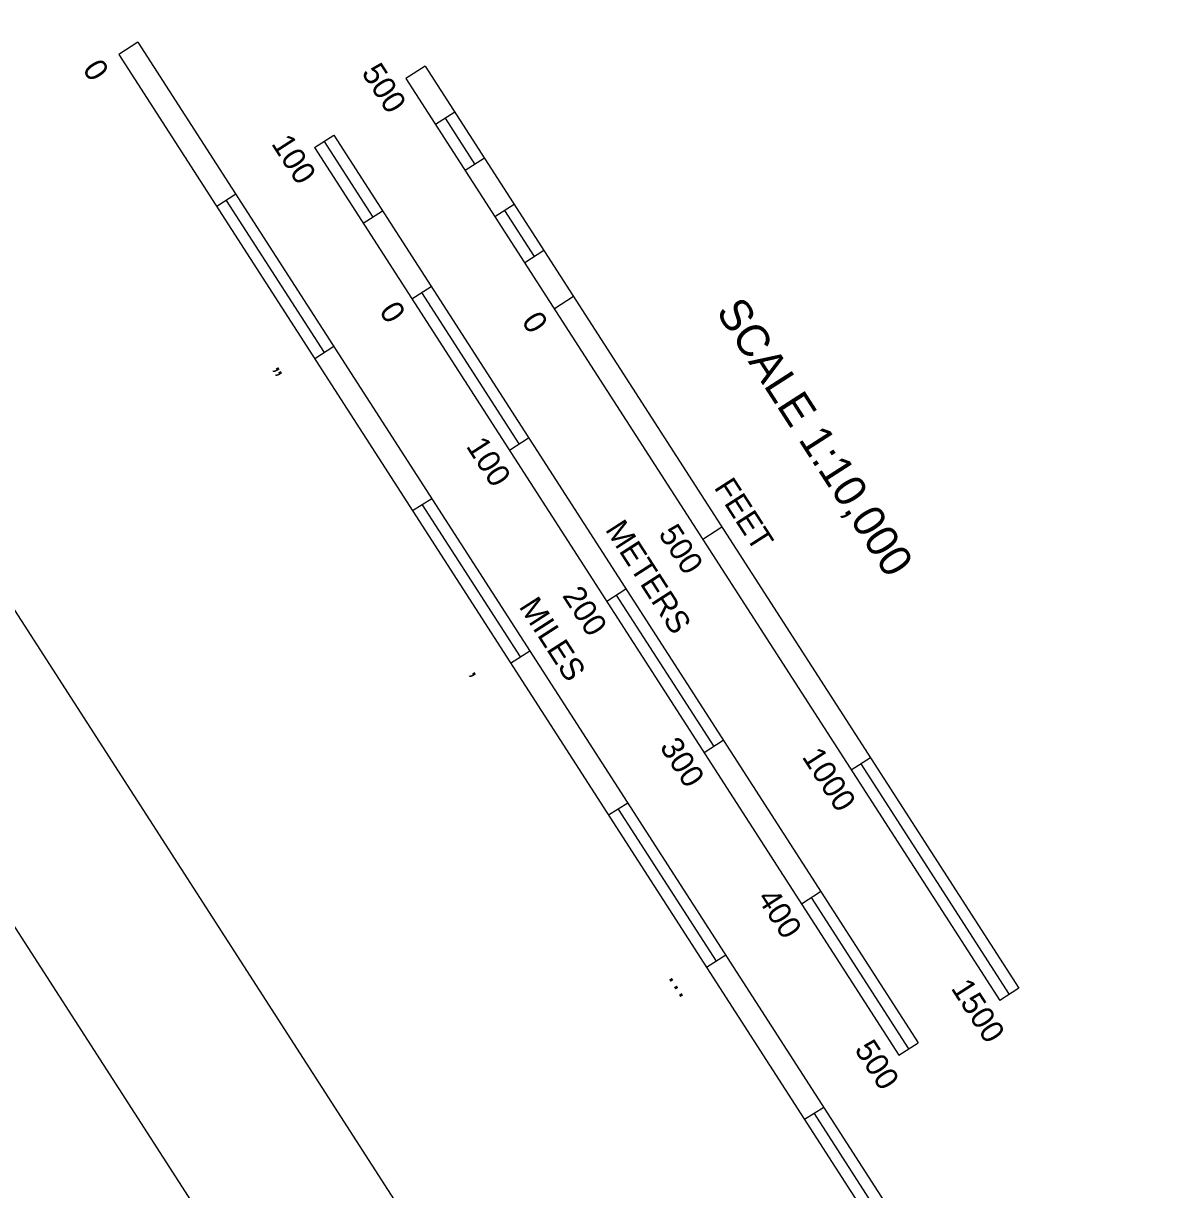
# Model space of a CAD drawing. Extents: x 3937982 to 3958556, y 219448 to 241894.
# Drawn here: x 3943396 to 3945496, y 226625 to 228752 of the extents above; entities that cross this region are included whole.
import ezdxf

# ---------------------------------------------------------------- set-up
doc = ezdxf.new("R2010")
doc.units = 0
doc.layers.add('G-ANNO-NPLT', color=7, linetype='Continuous')
doc.layers.add('V-ANNO-SYMB', color=7, linetype='Continuous')

msp = doc.modelspace()

# ---------------------------------------------------------------- linework, layer by layer
at = {"layer": 'G-ANNO-NPLT'}
msp.add_lwpolyline([(3938227.293, 235108.722), (3948150.136, 219692.877), (3958310.581, 226232.933), (3948387.738, 241648.778)], close=True, dxfattribs=at)
at = {"layer": 'V-ANNO-SYMB'}
for p, q in [((3943604.445, 228717.871), (3943569.551, 228695.409)), ((3943604.445, 228717.871), (3945033.336, 226497.99)), ((3943569.551, 228695.409), (3944998.439, 226475.528)), ((3944128.003, 228674.314), (3944093.108, 228651.852)), ((3944128.003, 228674.314), (3945210.495, 226992.586)), ((3944093.107, 228651.853), (3945175.599, 226970.124)), ((3944182.128, 228590.228), (3944147.232, 228567.766)), ((3944164.68, 228578.997), (3944218.804, 228494.911)), ((3943926.594, 228525.642), (3943961.489, 228548.105)), ((3943944.04, 228536.872), (3944032.805, 228398.973)), ((3943961.489, 228548.105), (3945026.661, 226893.284)), ((3943926.593, 228525.643), (3944991.766, 226870.822)), ((3944236.252, 228506.141), (3944201.356, 228483.681)), ((3943783.057, 228440.387), (3943748.161, 228417.924)), ((3943765.609, 228429.155), (3943944.22, 228151.67)), ((3944015.36, 228387.744), (3944050.257, 228410.205)), ((3944290.377, 228422.055), (3944255.481, 228399.593)), ((3944272.929, 228410.824), (3944327.054, 228326.738)), ((3944344.502, 228337.969), (3944309.606, 228315.507)), ((3944104.122, 228249.841), (3944139.018, 228272.301)), ((3944121.57, 228261.071), (3944299.099, 227985.267)), ((3944398.627, 228253.881), (3944363.731, 228231.42)), ((3943961.668, 228162.901), (3943926.772, 228140.439)), ((3944281.65, 227974.037), (3944316.547, 227996.498)), ((3944140.278, 227885.416), (3944105.383, 227862.954)), ((3944122.831, 227874.186), (3944301.443, 227596.699)), ((3944669.249, 227833.45), (3944634.353, 227810.989)), ((3944459.181, 227698.231), (3944494.075, 227720.694)), ((3944476.628, 227709.463), (3944654.156, 227433.661)), ((3944283.994, 227585.47), (3944318.89, 227607.93)), ((3944636.707, 227422.431), (3944671.604, 227444.891)), ((3944939.872, 227413.018), (3944904.976, 227390.556)), ((3944922.424, 227401.787), (3945193.047, 226981.355)), ((3944497.501, 227330.445), (3944462.605, 227307.983)), ((3944480.053, 227319.214), (3944658.665, 227041.729)), ((3944814.238, 227146.624), (3944849.133, 227169.087)), ((3944831.685, 227157.856), (3945009.214, 226882.052)), ((3944676.113, 227052.959), (3944641.217, 227030.498)), ((3945210.495, 226992.586), (3945175.599, 226970.124)), ((3944991.767, 226870.821), (3945026.661, 226893.284)), ((3944854.724, 226775.474), (3944819.828, 226753.013)), ((3944837.278, 226764.244), (3945015.887, 226486.759))]:
    msp.add_line(p, q, dxfattribs=at)
msp.add_lwpolyline([(3939234.332, 234121.63), (3948187.407, 220212.388), (3957822.273, 226414.141), (3948869.197, 240323.382), (3939234.332, 234121.63)], dxfattribs=at)

# ---------------------------------------------------------------- texts
for s, height, p in [('0', 41.5, (3943502.366, 228669.07)), ('500', 41.5, (3944011.1, 228662.213)), ('100', 41.5, (3943846.71, 228532.705)), ('0', 41.5, (3944043.158, 228227.507)), ('SCALE 1:10,000', 58.35, (3944657.274, 228226.789)), ('0', 41.5, (3944302.767, 228209.084)), ('„', 38.903, (3943854.612, 228124.227)), ('100', 41.5, (3944201.762, 227981.104)), ('FEET', 41.5, (3944653.722, 227905.84)), ('METERS', 41.5, (3944455.38, 227829.081)), ('500', 41.5, (3944552.343, 227821.354)), ('200', 41.5, (3944377.174, 227708.592)), ('MILES', 41.5, (3944298.066, 227688.55)), ('‚', 38.903, (3944211.835, 227569.257)), ('300', 41.5, (3944554.697, 227432.796)), ('1000', 41.5, (3944814.124, 227414.657)), ('400', 41.5, (3944732.231, 227156.985)), ('…', 38.903, (3944569.057, 227014.286)), ('1500', 41.5, (3945085.631, 226992.851)), ('500', 41.5, (3944909.76, 226881.181))]:
    msp.add_text(s, height=height, rotation=302.768522, dxfattribs=at).set_placement(p)

doc.saveas('drawing.dxf')
